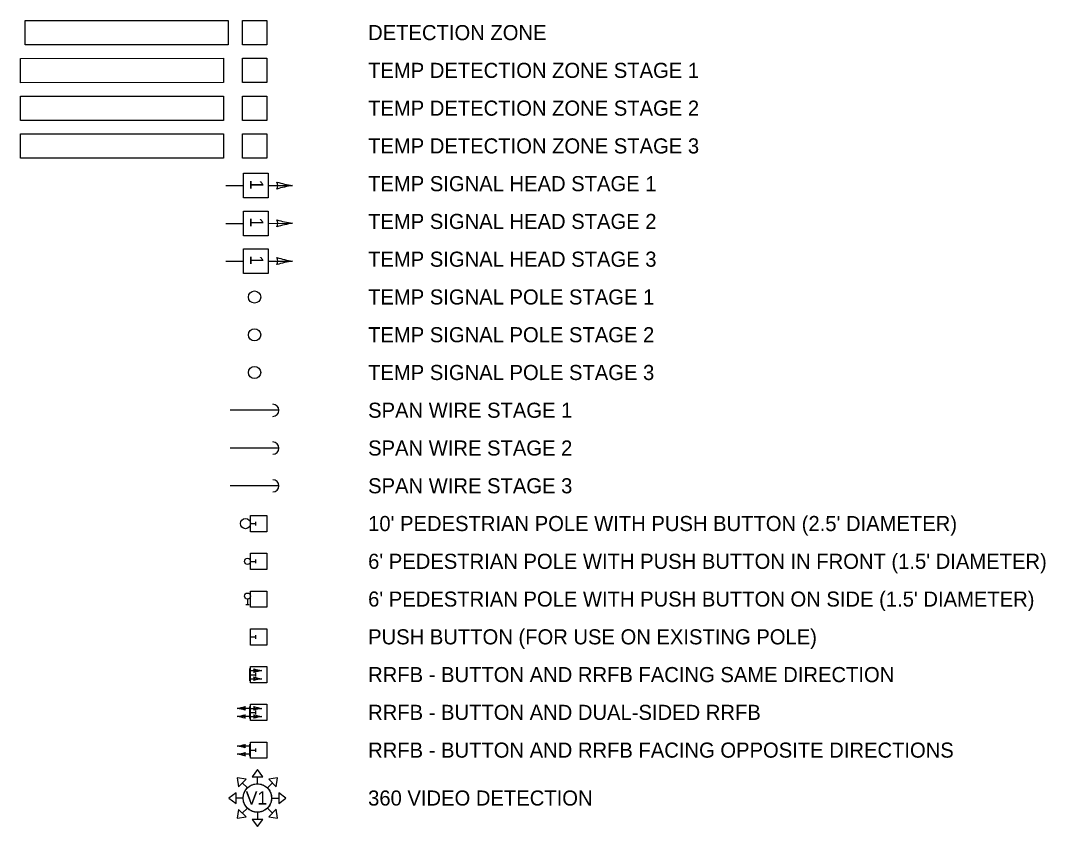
# Model space of a CAD drawing. Extents: x 994024 to 994914, y 1985815 to 1986420.
# Drawn here: x 994024.2 to 994276.7, y 1986017.7 to 1986216.2 of the extents above; entities that cross this region are included whole.
import ezdxf

# ---------------------------------------------------------------- set-up
doc = ezdxf.new("R2010")
doc.units = 0
for name, color, linetype in [('_CIVIL_CONSTRUCTION', 7, 'Continuous'), ('DSN_RDWY_Alignment Annotation', 7, 'Continuous'), ('DSN_ROW_Line-Annotation', 7, 'Continuous'), ('DSN_ROW_Point', 7, 'Continuous'), ('EX_ALIGNMENT', 7, 'Continuous'), ('EX_ROW', 7, 'Continuous'), ('EX_ROW_Annotation', 7, 'Continuous'), ('S_CURB', 7, 'Continuous'), ('S_DRIVEWAY', 7, 'Continuous'), ('S_DROP_INLET', 7, 'Continuous'), ('S_HWY_SYMBOLS', 7, 'Continuous'), ('S_HWY_TEXT', 7, 'Continuous'), ('S_ORTHO_IMAGE', 7, 'Continuous'), ('S_SIDEWALK', 7, 'Continuous'), ('S_WALL', 7, 'Continuous')]:
    doc.layers.add(name, color=color, linetype=linetype)

msp = doc.modelspace()

# ---------------------------------------------------------------- linework, layer by layer
at = {"layer": '_CIVIL_CONSTRUCTION'}
for p, q in [((994024.24, 1986197.53), (994074.24, 1986197.56)), ((994024.24, 1986191.53), (994024.24, 1986197.53)), ((994074.24, 1986197.56), (994074.24, 1986191.56)), ((994074.24, 1986191.56), (994024.24, 1986191.53))]:
    msp.add_line(p, q, dxfattribs=at)
msp.add_lwpolyline([(994084.91, 1986191.56), (994078.91, 1986191.56), (994078.91, 1986197.56), (994084.91, 1986197.56)], close=True, dxfattribs=at)
at = {"layer": 'DSN_RDWY_Alignment Annotation'}
for p, q in [((994074.8, 1986175.49), (994079.14, 1986175.49)), ((994085.21, 1986175.51), (994091.25, 1986175.52))]:
    msp.add_line(p, q, dxfattribs=at)
msp.add_lwpolyline([(994079.15, 1986172.47), (994079.14, 1986178.54), (994085.21, 1986178.54), (994085.21, 1986172.47)], close=True, dxfattribs=at)
for centre, radius, start, end in [((994085.98, 1986175.51), 1.63, 328.1778, 31.8725), ((994095.65, 1986204.66), 29.47, 253.6787, 261.4168), ((994095.67, 1986146.38), 29.47, 98.6335, 106.3716)]:
    msp.add_arc(centre, radius, start, end, dxfattribs=at)
at = {"layer": 'DSN_ROW_Line-Annotation'}
msp.add_line((994087.91, 1986101.57), (994075.91, 1986101.56), dxfattribs=at)
msp.add_circle((994081.9, 1986129.46), 1.5, dxfattribs=at)
msp.add_arc((994086.41, 1986101.56), 1.5, 270.0252, 90.0252, dxfattribs=at)
at = {"layer": 'DSN_ROW_Point'}
for p, q in [((994074.8, 1986166.19), (994079.14, 1986166.19)), ((994085.21, 1986166.21), (994091.25, 1986166.22))]:
    msp.add_line(p, q, dxfattribs=at)
msp.add_lwpolyline([(994079.15, 1986163.17), (994079.14, 1986169.24), (994085.21, 1986169.24), (994085.21, 1986163.17)], close=True, dxfattribs=at)
for centre, radius, start, end in [((994085.98, 1986166.21), 1.63, 328.1778, 31.8725), ((994095.65, 1986195.36), 29.47, 253.6787, 261.4168), ((994095.67, 1986137.08), 29.47, 98.6335, 106.3716)]:
    msp.add_arc(centre, radius, start, end, dxfattribs=at)
at = {"layer": 'EX_ALIGNMENT'}
msp.add_line((994087.91, 1986110.87), (994075.91, 1986110.86), dxfattribs=at)
msp.add_circle((994081.9, 1986138.76), 1.5, dxfattribs=at)
msp.add_arc((994086.41, 1986110.86), 1.5, 270.0252, 90.0252, dxfattribs=at)
at = {"layer": 'EX_ROW'}
for p, q in [((994024.24, 1986188.23), (994074.24, 1986188.26)), ((994024.24, 1986182.23), (994024.24, 1986188.23)), ((994074.24, 1986188.26), (994074.24, 1986182.26)), ((994074.24, 1986182.26), (994024.24, 1986182.23))]:
    msp.add_line(p, q, dxfattribs=at)
msp.add_lwpolyline([(994084.91, 1986182.26), (994078.91, 1986182.26), (994078.91, 1986188.26), (994084.91, 1986188.26)], close=True, dxfattribs=at)
at = {"layer": 'EX_ROW_Annotation'}
for p, q in [((994074.8, 1986156.89), (994079.14, 1986156.89)), ((994085.21, 1986156.91), (994091.25, 1986156.92))]:
    msp.add_line(p, q, dxfattribs=at)
msp.add_lwpolyline([(994079.15, 1986153.87), (994079.14, 1986159.94), (994085.21, 1986159.94), (994085.21, 1986153.87)], close=True, dxfattribs=at)
for centre, radius, start, end in [((994085.98, 1986156.91), 1.63, 328.1778, 31.8725), ((994095.65, 1986186.06), 29.47, 253.6787, 261.4168), ((994095.67, 1986127.78), 29.47, 98.6335, 106.3716)]:
    msp.add_arc(centre, radius, start, end, dxfattribs=at)
at = {"layer": 'S_CURB'}
for p, q in [((994080.66, 1986056.56), (994080.66, 1986053.56)), ((994080.66, 1986056.06), (994083.68, 1986056.06)), ((994080.66, 1986055.18), (994080.66, 1986054.93)), ((994080.66, 1986055.18), (994080.91, 1986055.18)), ((994080.91, 1986054.93), (994080.66, 1986054.93)), ((994080.91, 1986054.93), (994080.91, 1986055.18)), ((994080.66, 1986054.06), (994083.68, 1986054.06)), ((994080.66, 1986047.26), (994080.66, 1986044.26)), ((994080.66, 1986046.76), (994077.64, 1986046.76)), ((994080.66, 1986044.76), (994077.64, 1986044.76)), ((994080.66, 1986046.76), (994083.68, 1986046.76)), ((994080.66, 1986045.88), (994080.66, 1986045.63)), ((994080.66, 1986045.88), (994080.91, 1986045.88)), ((994080.91, 1986045.63), (994080.66, 1986045.63)), ((994080.66, 1986044.76), (994083.68, 1986044.76)), ((994080.91, 1986045.63), (994080.91, 1986045.88)), ((994080.66, 1986037.46), (994077.64, 1986037.46)), ((994080.66, 1986037.96), (994080.66, 1986034.96)), ((994080.66, 1986035.46), (994077.64, 1986035.46)), ((994080.66, 1986036.58), (994080.66, 1986036.33)), ((994080.66, 1986036.58), (994080.91, 1986036.58)), ((994080.91, 1986036.33), (994080.66, 1986036.33)), ((994080.91, 1986036.33), (994080.91, 1986036.58))]:
    msp.add_line(p, q, dxfattribs=at)
for centre, radius in [((994081.9, 1986148.06), 1.5), ((994079.66, 1986092.26), 1.25), ((994080.16, 1986082.96), 0.75), ((994080.16, 1986074.41), 0.75)]:
    msp.add_circle(centre, radius, dxfattribs=at)
for centre, radius, start, end in [((994081.05, 1986056.06), 0.814, 328.1778, 31.8725), ((994085.88, 1986070.63), 14.74, 253.6787, 261.4168), ((994085.89, 1986041.49), 14.74, 98.6335, 106.3716), ((994081.05, 1986054.06), 0.814, 328.1778, 31.8725), ((994085.88, 1986068.63), 14.74, 253.6787, 261.4168), ((994085.89, 1986039.49), 14.74, 98.6335, 106.3716), ((994075.43, 1986061.33), 14.74, 278.6335, 286.3716), ((994080.27, 1986046.76), 0.814, 148.1778, 211.8725), ((994081.05, 1986046.76), 0.814, 328.1778, 31.8725), ((994085.88, 1986061.33), 14.74, 253.6787, 261.4168), ((994075.44, 1986032.19), 14.74, 73.6787, 81.4168), ((994075.43, 1986059.33), 14.74, 278.6335, 286.3716), ((994075.44, 1986030.19), 14.74, 73.6787, 81.4168), ((994080.27, 1986044.76), 0.814, 148.1778, 211.8725), ((994085.89, 1986032.19), 14.74, 98.6335, 106.3716), ((994081.05, 1986044.76), 0.814, 328.1778, 31.8725), ((994085.88, 1986059.33), 14.74, 253.6787, 261.4168), ((994085.89, 1986030.19), 14.74, 98.6335, 106.3716), ((994075.43, 1986052.03), 14.74, 278.6335, 286.3716), ((994075.44, 1986022.89), 14.74, 73.6787, 81.4168), ((994080.27, 1986037.46), 0.814, 148.1778, 211.8725), ((994075.43, 1986050.03), 14.74, 278.6335, 286.3716), ((994075.44, 1986020.89), 14.74, 73.6787, 81.4168), ((994080.27, 1986035.46), 0.814, 148.1778, 211.8725)]:
    msp.add_arc(centre, radius, start, end, dxfattribs=at)
at = {"layer": 'S_DRIVEWAY'}
for p, q in [((994080.91, 1986092.26), (994082.23, 1986092.26)), ((994082.23, 1986091.82), (994082.23, 1986092.7)), ((994080.91, 1986082.96), (994082.23, 1986082.96)), ((994082.23, 1986082.52), (994082.23, 1986083.4)), ((994079.72, 1986072.34), (994080.6, 1986072.34)), ((994080.16, 1986073.66), (994080.16, 1986072.34)), ((994082.23, 1986063.92), (994082.23, 1986064.8)), ((994080.91, 1986064.36), (994082.23, 1986064.36)), ((994080.91, 1986055.06), (994082.23, 1986055.06)), ((994082.23, 1986054.62), (994082.23, 1986055.5)), ((994080.91, 1986045.76), (994082.23, 1986045.76)), ((994082.23, 1986045.32), (994082.23, 1986046.2)), ((994082.23, 1986036.02), (994082.23, 1986036.9)), ((994080.91, 1986036.46), (994082.23, 1986036.46))]:
    msp.add_line(p, q, dxfattribs=at)
at = {"layer": 'S_DROP_INLET'}
for points in [[(994080.91, 1986094.26), (994084.91, 1986094.26), (994084.91, 1986090.26), (994080.91, 1986090.26)], [(994080.91, 1986084.96), (994084.91, 1986084.96), (994084.91, 1986080.96), (994080.91, 1986080.96)], [(994080.91, 1986075.66), (994084.91, 1986075.66), (994084.91, 1986071.66), (994080.91, 1986071.66)], [(994080.91, 1986066.36), (994084.91, 1986066.36), (994084.91, 1986062.36), (994080.91, 1986062.36)], [(994080.91, 1986057.06), (994084.91, 1986057.06), (994084.91, 1986053.06), (994080.91, 1986053.06)], [(994080.91, 1986047.76), (994084.91, 1986047.76), (994084.91, 1986043.76), (994080.91, 1986043.76)], [(994080.91, 1986038.46), (994084.91, 1986038.46), (994084.91, 1986034.46), (994080.91, 1986034.46)]]:
    msp.add_lwpolyline(points, close=True, dxfattribs=at)
at = {"layer": 'S_HWY_SYMBOLS'}
for p, q in [((994024.24, 1986206.83), (994074.24, 1986206.86)), ((994024.24, 1986200.83), (994024.24, 1986206.83)), ((994074.24, 1986206.86), (994074.24, 1986200.86)), ((994074.24, 1986200.86), (994024.24, 1986200.83))]:
    msp.add_line(p, q, dxfattribs=at)
msp.add_lwpolyline([(994084.91, 1986200.86), (994078.91, 1986200.86), (994078.91, 1986206.86), (994084.91, 1986206.86)], close=True, dxfattribs=at)
at = {"layer": 'S_HWY_TEXT'}
msp.add_line((994087.91, 1986120.17), (994075.91, 1986120.16), dxfattribs=at)
msp.add_arc((994086.41, 1986120.16), 1.5, 270.0252, 90.0252, dxfattribs=at)
at = {"layer": 'S_SIDEWALK'}
for p, q in [((994082.59, 1986031.69), (994081.28, 1986029.93)), ((994083.9, 1986029.93), (994082.59, 1986031.69)), ((994079.81, 1986029.32), (994077.63, 1986029.63)), ((994077.63, 1986029.63), (994077.95, 1986027.46)), ((994077.95, 1986027.46), (994079.81, 1986029.32)), ((994081.28, 1986029.93), (994083.9, 1986029.93)), ((994082.59, 1986028.18), (994082.59, 1986029.93)), ((994087.55, 1986029.64), (994085.37, 1986029.32)), ((994085.37, 1986029.32), (994087.23, 1986027.46)), ((994087.23, 1986027.46), (994087.55, 1986029.64)), ((994080.12, 1986027.15), (994078.88, 1986028.39)), ((994085.07, 1986027.15), (994086.3, 1986028.39)), ((994077.34, 1986025.99), (994075.58, 1986024.68)), ((994075.58, 1986024.68), (994077.34, 1986023.37)), ((994077.34, 1986023.37), (994077.34, 1986025.99)), ((994079.09, 1986024.68), (994077.34, 1986024.68)), ((994086.09, 1986024.68), (994087.84, 1986024.68)), ((994087.84, 1986025.99), (994087.84, 1986023.37)), ((994089.6, 1986024.68), (994087.84, 1986025.99)), ((994087.84, 1986023.37), (994089.6, 1986024.68)), ((994077.95, 1986021.89), (994077.64, 1986019.72)), ((994079.81, 1986020.04), (994077.95, 1986021.89)), ((994080.12, 1986022.2), (994078.88, 1986020.97)), ((994085.07, 1986022.2), (994086.3, 1986020.97)), ((994087.23, 1986021.9), (994085.38, 1986020.04)), ((994087.55, 1986019.72), (994087.23, 1986021.9)), ((994077.64, 1986019.72), (994079.81, 1986020.04)), ((994083.9, 1986019.43), (994081.28, 1986019.43)), ((994081.28, 1986019.43), (994082.59, 1986017.67)), ((994082.59, 1986021.18), (994082.59, 1986019.43)), ((994082.59, 1986017.67), (994083.9, 1986019.43)), ((994085.38, 1986020.04), (994087.55, 1986019.72))]:
    msp.add_line(p, q, dxfattribs=at)
msp.add_lwpolyline([(994079.91, 1986026.93), (994080.11, 1986027.15), (994080.34, 1986027.36), (994080.58, 1986027.54), (994080.84, 1986027.71), (994081.11, 1986027.85), (994081.39, 1986027.97), (994081.68, 1986028.06), (994081.98, 1986028.12), (994082.28, 1986028.16), (994082.59, 1986028.18), (994082.89, 1986028.17), (994083.19, 1986028.13), (994083.49, 1986028.06), (994083.78, 1986027.97), (994084.07, 1986027.85), (994084.34, 1986027.71), (994084.59, 1986027.55), (994084.84, 1986027.36), (994085.07, 1986027.15), (994085.27, 1986026.93), (994085.46, 1986026.69), (994085.62, 1986026.43), (994085.76, 1986026.16), (994085.88, 1986025.88), (994085.97, 1986025.59), (994086.04, 1986025.29), (994086.08, 1986024.98), (994086.09, 1986024.68), (994086.08, 1986024.37), (994086.04, 1986024.07), (994085.97, 1986023.77), (994085.88, 1986023.48), (994085.76, 1986023.2), (994085.62, 1986022.93), (994085.46, 1986022.67), (994085.27, 1986022.43), (994085.07, 1986022.2), (994084.84, 1986022), (994084.84, 1986022), (994084.6, 1986021.81), (994084.34, 1986021.65), (994084.07, 1986021.51), (994083.79, 1986021.39), (994083.5, 1986021.3), (994083.2, 1986021.23), (994082.9, 1986021.19), (994082.59, 1986021.18), (994082.29, 1986021.19), (994081.99, 1986021.23), (994081.69, 1986021.3), (994081.4, 1986021.39), (994081.11, 1986021.51), (994080.84, 1986021.65), (994080.59, 1986021.81), (994080.34, 1986022), (994080.12, 1986022.2), (994079.91, 1986022.43), (994079.73, 1986022.67), (994079.56, 1986022.93), (994079.42, 1986023.2), (994079.3, 1986023.48), (994079.21, 1986023.77), (994079.15, 1986024.07), (994079.11, 1986024.37), (994079.09, 1986024.68), (994079.11, 1986024.98), (994079.14, 1986025.28), (994079.21, 1986025.58), (994079.3, 1986025.87), (994079.42, 1986026.16), (994079.56, 1986026.43), (994079.72, 1986026.68)], close=True, dxfattribs=at)
msp.add_circle((994082.59, 1986024.68), 3.5, dxfattribs=at)
at = {"layer": 'S_WALL'}
for p, q in [((994025.39, 1986216.13), (994075.39, 1986216.16)), ((994025.39, 1986210.13), (994025.39, 1986216.13)), ((994075.39, 1986216.16), (994075.39, 1986210.16)), ((994075.39, 1986210.16), (994025.39, 1986210.13))]:
    msp.add_line(p, q, dxfattribs=at)
msp.add_lwpolyline([(994084.91, 1986210.16), (994078.91, 1986210.16), (994078.91, 1986216.16), (994084.91, 1986216.16)], close=True, dxfattribs=at)

# ---------------------------------------------------------------- texts
at = {"layer": 'DSN_RDWY_Alignment Annotation'}
msp.add_text('1', height=3.25, rotation=270.0252, dxfattribs=at).set_placement((994080.8, 1986176.97))
at = {"layer": 'DSN_ROW_Point'}
msp.add_text('1', height=3.25, rotation=270.0252, dxfattribs=at).set_placement((994080.8, 1986167.67))
at = {"layer": 'EX_ROW_Annotation'}
msp.add_text('1', height=3.25, rotation=270.0252, dxfattribs=at).set_placement((994080.8, 1986158.37))
at = {"layer": 'S_ORTHO_IMAGE'}
for s, p in [('DETECTION ZONE', (994109.87, 1986211.32)), ('TEMP DETECTION ZONE STAGE 1', (994109.87, 1986202.02)), ('TEMP DETECTION ZONE STAGE 2', (994109.87, 1986192.72)), ('TEMP DETECTION ZONE STAGE 3', (994109.87, 1986183.42)), ('TEMP SIGNAL HEAD STAGE 1', (994109.87, 1986174.12)), ('TEMP SIGNAL HEAD STAGE 2', (994109.87, 1986164.82)), ('TEMP SIGNAL HEAD STAGE 3', (994109.87, 1986155.52)), ('TEMP SIGNAL POLE STAGE 1', (994109.87, 1986146.22)), ('TEMP SIGNAL POLE STAGE 2', (994109.87, 1986136.92)), ('TEMP SIGNAL POLE STAGE 3', (994109.87, 1986127.62)), ('SPAN WIRE STAGE 1', (994109.87, 1986118.32)), ('SPAN WIRE STAGE 2', (994109.87, 1986109.02)), ('SPAN WIRE STAGE 3', (994109.87, 1986099.72)), ("10' PEDESTRIAN POLE WITH PUSH BUTTON (2.5' DIAMETER)", (994109.87, 1986090.42)), ("6' PEDESTRIAN POLE WITH PUSH BUTTON IN FRONT (1.5' DIAMETER)", (994109.87, 1986081.12)), ("6' PEDESTRIAN POLE WITH PUSH BUTTON ON SIDE (1.5' DIAMETER)", (994109.87, 1986071.82)), ('PUSH BUTTON (FOR USE ON EXISTING POLE)', (994109.87, 1986062.52)), ('RRFB - BUTTON AND RRFB FACING SAME DIRECTION', (994109.87, 1986053.22)), ('RRFB - BUTTON AND DUAL-SIDED RRFB', (994109.87, 1986043.92)), ('RRFB - BUTTON AND RRFB FACING OPPOSITE DIRECTIONS', (994109.87, 1986034.62)), ('360 VIDEO DETECTION', (994109.87, 1986022.82))]:
    msp.add_text(s, height=3.72, dxfattribs=at).set_placement(p)
at = {"layer": 'S_SIDEWALK'}
msp.add_text('V1', height=3.25, rotation=0.0252, dxfattribs=at).set_placement((994079.71, 1986023.08))

doc.saveas('drawing.dxf')
